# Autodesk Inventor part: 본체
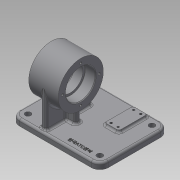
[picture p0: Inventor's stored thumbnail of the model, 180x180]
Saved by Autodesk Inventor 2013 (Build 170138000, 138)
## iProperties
Created: 2019-09
Part Number: 본체
Material: 알루미늄 6061
Document SubType Name: Modeling
Designer: mduedu
Density: 2.71 g/cm^3
Mass: 561.4 g
Surface Area: 499.749 cm^2
Volume: 207.159 cm^3
Author: mduedu
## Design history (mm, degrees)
sketch "스케치1"
  geometry: L1 (42, -62)-(-84, -62); L2 (-84, -62)-(-84, 36); L3 (-84, 36)-(42, 36); L4 (42, 36)-(42, -62); 1 further point
  constraints: 8 end point, 2 parallel, 1 horizontal, 1 perpendicular
  dimensions: "d0" = 36 distance from line of L3 point (0, 0); "d1" = 98 distance of L1.end L2.end; "d2" = 42 distance from line of L4 point (0, 0); "d3" = 126 distance of L2.end L3.end
extrude "돌출1" new body sketch "스케치1" distance "d4" = 9; taper "d5" = 0 deg
sketch "스케치2"
  geometry: L1 (0, -62)-(0, 36) reference; C1 r 32 at (59, 0); 1 further point
  constraints: 1 centre point, 1 horizontal alignment
  dimensions: "d6" = 64 diameter of C1; "d7" = 59 distance from line of L1 C1.centre
extrude "돌출2" join sketch "스케치2" stored distance "d8" = 42; taper "d9" = 0 deg
sketch "스케치3"
  geometry: L1 (-17, 4)-(17, 4); L2 (17, 4)-(17, -4); L3 (17, -4)-(-17, -4); L4 (-17, -4)-(-17, 4); L5 (-4, 32)-(4, 32); L6 (4, 32)-(4, -32); L7 (4, -32)-(-4, -32); L8 (-4, -32)-(-4, 32); 5 further points
  constraints: 16 end point, 4 midpoint, 4 parallel, 2 horizontal, 2 horizontal alignment, 2 perpendicular, 2 vertical alignment
  dimensions: "d10" = 8 distance of L5.start L5.end; "d12" = 8 distance of L1.end L2.end; "d13" = 34 distance of L2.end L3.end; "d14" = 64 distance of L5.end L6.end
extrude "돌출3" join sketch "스케치3" stored distance "d15" = 42; taper "d16" = 0 deg
sketch "스케치4"
  geometry: C1 r 32 at (0, 0) reference; C2 r 21 at (0, 0); 1 further point
  constraints: 1 centre point, 1 coincident
  dimensions: "d17" = 42 diameter of C2
extrude "돌출4" cut sketch "스케치4" distance "d18" = 15; taper "d19" = 0 deg
hole "구멍1" diameter "d22" = 36; stored, may be unused: countersink angle "d26" = 90 deg, drill point angle "d28" = 118 deg; dims "d20" = 10, "d21" = 10, "d23" = 6, "d24" = 4, "d25" = 2, "d27" = 8
fillet "모깎기1" dims "d29" = 0.3
chamfer "모따기1" distance "d30" = 1; stored, may be unused: second distance "d31" = 2, angle "d32" = 45 deg
sketch "스케치5" dims "d33" = 52
  geometry: C1 r 32 at (0, 0) reference; 3 further points
  constraints: 2 vertical alignment, 1 coincident, 2 other
hole "구멍2" sketch "스케치5" at (0, 26) diameter "d34" = 3.242; stored, may be unused: countersink angle "d38" = 90 deg, drill point angle "d40" = 118 deg; dims "d35" = 8, "d36" = 4, "d37" = 2, "d39" = 10
fillet "모깎기2" dims "d44" = 12
sketch "스케치6"
  geometry: L1 (-42, 50)-(-42, -24) reference; L2 (-30, -36)-(72, -36) reference; L3 (84, -24)-(84, 50) reference; L4 (72, 62)-(-30, 62) reference; L5 (17, 4)-(17, -4) reference; L6 (17, -4)-(4, -4) reference; L7 (4, -4)-(4, -32) reference; L8 (4, -32)-(-4, -32) reference; L9 (-4, -32)-(-4, -4) reference; L10 (-4, -4)-(-17, -4) reference; L11 (-17, -4)-(-17, 4) reference; L12 (-17, 4)-(-4, 4) reference; L13 (-4, 4)-(-4, 32) reference; L14 (-4, 32)-(4, 32) reference; L15 (4, 32)-(4, 4) reference; L16 (4, 4)-(17, 4) reference; A1 r 12 centre (-30, 50) between (-30, 62) and (-42, 50) reference; A2 r 12 centre (-30, -24) between (-42, -24) and (-30, -36) reference; A3 r 12 centre (72, -24) between (72, -36) and (84, -24) reference; A4 r 12 centre (72, 50) between (84, 50) and (72, 62) reference; 5 further points
  constraints: 4 coincident
hole "구멍3" sketch "스케치6" at (-30, 50), (72, 50), (72, -24), (-30, -24) diameter "d45" = 8; stored, may be unused: countersink angle "d49" = 90 deg, drill point angle "d51" = 118 deg; dims "d46" = 8, "d47" = 4, "d48" = 2, "d50" = 10
sketch "스케치7"
  geometry: L1 (38, 57)-(58, 57); L2 (58, 57)-(58, 17); L3 (58, 17)-(38, 17); L4 (38, 17)-(38, 57); L5 (72, 62)-(-30, 62) reference; 3 further points
  constraints: 8 end point, 2 midpoint, 2 parallel, 1 horizontal, 1 perpendicular
  dimensions: "d52" = 48 horizontal distance of point (48, 57) point (0, 0); "d53" = 20 distance of L1.start L1.end; "d54" = 40 distance of L1.end L2.end; "d55" = 25 distance from line of point (38, 37) L5
extrude "돌출5" join sketch "스케치7" distance "d56" = 3; taper "d57" = 0 deg
fillet "모깎기3" dims "d58" = 3
fillet "모깎기4" dims "d59" = 3
fillet "모깎기5" dims "d60" = 3
fillet "모깎기6" dims "d61" = 3
fillet "모깎기7" dims "d62" = 3
fillet "모깎기8" dims "d63" = 3
sketch "스케치8"
  geometry: L1 (72, 62)-(58.317, 62) reference; L2 (84, -24)-(84, 50) reference; C1 r 1.5 at (43, 53); C2 r 1.5 at (53, 21); 1 further point
  constraints: 2 centre point, 1 equal radius
  dimensions: "d64" = 3 diameter of C1; "d65" = 9 distance from line of C1.centre L1; "d66" = 32 vertical distance of C2.centre C1.centre; "d67" = 10 horizontal distance of C2.centre C1.centre; "d68" = 31 distance from line of L2 C2.centre
hole "구멍4" sketch "스케치8" at (43, 53), (53, 21) diameter "d69" = 3; stored, may be unused: countersink angle "d73" = 90 deg, drill point angle "d75" = 118 deg; dims "d70" = 8, "d71" = 4, "d72" = 2, "d74" = 6
sketch "스케치9"
  geometry: C1 r 1.5 at (43, 53) reference; C2 r 1.5 at (53, 21) reference; 3 further points
  constraints: 2 horizontal alignment, 2 vertical alignment
hole "구멍5" sketch "스케치9" at (53, 53), (43, 21) diameter "d76" = 3.242; stored, may be unused: countersink angle "d80" = 90 deg, drill point angle "d82" = 118 deg; dims "d77" = 6, "d78" = 4, "d79" = 2, "d81" = 8
sketch "스케치10"
  geometry: L1 (-30, -36)-(72, -36) reference; L2 (84, -24)-(84, 50) reference; 2 further points
  constraints: 1 other
  dimensions: "d83" = 10 distance from line of point (46, -26) L1; "d84" = 38 distance from line of point (46, -26) L2
feature "엠보싱1" sketch "스케치10" dims "d0" = 36, "d1" = 98, "d2" = 42, "d3" = 126, "d10" = 8, "d14" = 64, "d85" = 0.5, "d86" = 0
node "솔리드1"
mirror "대칭1"
pattern_circular "원형 패턴1" dims angle "d42" = 360 deg
mirror "대칭2"
node "투영된 루프1"
